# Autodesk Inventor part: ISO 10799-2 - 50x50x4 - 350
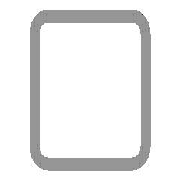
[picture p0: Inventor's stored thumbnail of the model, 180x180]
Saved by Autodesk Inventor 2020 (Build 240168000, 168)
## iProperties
Created: 2019-01
Part Number: ISO 10799-2 - 50x50x4 - 350
Material: Ocel
Description: Konstrukční oceli – za studena tvarované, svařované, stavební duté profily
Document SubType Name: Modeling
Standard: ISO 10799-2
Designer: doma
Standard Revision: First edition 2011-09-15
Standards Organization: ISO
Language: cs-CZ
Size Designation: 50x50x4 - 350
Categories: <MemberInstance><Categories><Category DisplayName="Konstrukční profily" InternalName="089c4875-fa83-4c05-b084-43b9cc11f5ed" Mnemonic="GRDR"><CategoryParameter D
Stock Number: 50x50x4
Density: 7.85 g/cm^3
Appearance: Plech
Mass: 2045.31 g
Surface Area: 1316.64 cm^2
Volume: 260.549 cm^3
IsCustomPart: 1
G_L: 350,000 mm
Author: doma
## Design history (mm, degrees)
node "Počáteční rovina"
node "Koncová rovina"
sketch "Náčrt"
  geometry: L1 (-25, -17)-(-25, 17); L2 (-17, 25)-(17, 25); L3 (25, 17)-(25, -17); L4 (17, -25)-(-17, -25); L5 (-17, 21)-(17, 21); L6 (21, 17)-(21, -17); L7 (17, -21)-(-17, -21); L8 (-21, -17)-(-21, 17); L9 (0, 37.32)-(0, -37.32) reference; L10 (-37.32, 0)-(37.32, 0) reference; A1 r 8 centre (-17, -17) between (-25, -17) and (-17, -25); A2 r 8 centre (17, 17) between (25, 17) and (17, 25); A3 r 8 centre (-17, 17) between (-17, 25) and (-25, 17); A4 r 8 centre (17, -17) between (17, -25) and (25, -17); A5 r 4 centre (-17, 17) between (-17, 21) and (-21, 17); A6 r 4 centre (17, 17) between (21, 17) and (17, 21); A7 r 4 centre (17, -17) between (17, -21) and (21, -17); A8 r 4 centre (-17, -17) between (-21, -17) and (-17, -21)
  constraints: 16 end point, 16 point on circle, 8 centre point, 8 tangent, 4 parallel, 3 equal radius, 2 perpendicular, 7 other
  dimensions: "d7" = 8 radius of A1 (= G_IR); "d9" = 50 distance between parallel lines of L1 L3 (= G_W); "d11" = 50 distance between parallel lines of L2 L4 (= G_H); "d12" = 4 distance between parallel lines of L3 L6 (= G_T); "d15" = 25 distance between parallel lines of L9 L3 (= 0.5 x d9); "d16" = 25 distance between parallel lines of L2 L10 (= 0.5 x d11)
extrude "Těleso" new body sketch "Náčrt" stored distance "d3" = 375; taper "d4" = 0 deg
node "Driven Length"
  sketch "Sketch3"
    geometry: L1 (0, 0)-(10, 0) reference
    constraints: 2 end point, 1 horizontal
  workplane "Work Plane3"
  sketch "Sketch4"
    geometry: L1 (-2, 0)-(12, 0) reference; L2 (-2, 350)-(12, 350) reference
    dimensions: "d18" = 350 distance between parallel lines of L1 L2 (derived)
body "Solid1"
other parameters: "G_W" = 50 [user parameter; used in 1 equation term], "G_H" = 50 [user parameter; used in 1 equation term], "G_T" = 4 [user parameter; used in 1 equation term], "G_IR" = 8 [user parameter; used in 1 equation term], "G_L" = 350 (= d18) [user parameter], "G_OFFSET_START" = 0 [user parameter; used in 1 equation term], "G_OFFSET_END" = 0 [user parameter; used in 1 equation term], "d13" = 0 (computed from G_OFFSET_START), "d17" = 90 deg, "MAS" = 0.545 [user parameter]
